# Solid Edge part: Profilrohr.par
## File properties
Username: bmolnar
Dokumentum tartalom típus: 0
Author: bmolnar
Last saved by: bmolnar
Revision: 90
Sűrűség: 0,000 kg/m^3
Pontosság: 0,990
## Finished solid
Body 1: solid body, 115 faces, 338 edges, 224 vertices.
  Faces by surface: cylinder 59, plane 56
  Edges by curve: line 220, circle 118
Bounding box of the edges (mm): 95.500 x 95.500 x 149.000, from (-47.75, -47.75, -120) to (47.75, 47.75, 29).
Cylindrical faces by radius (mm): R0.2 x24, R0.5 x24, R1 x4, R10 x4, R13.5 x2, R40 x1
Planar faces by outward normal: +x 13, +y 14, +z 1, -x 13, -y 14, -z 1
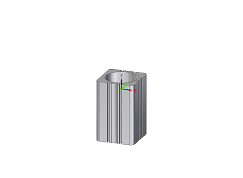
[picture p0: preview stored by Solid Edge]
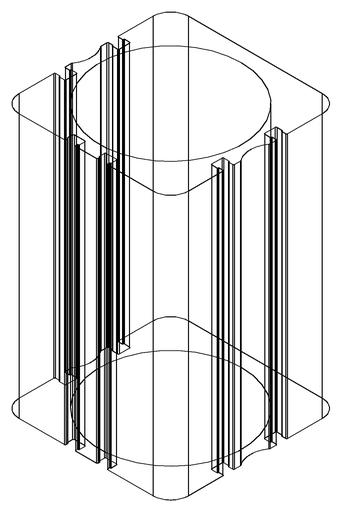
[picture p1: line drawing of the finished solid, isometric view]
